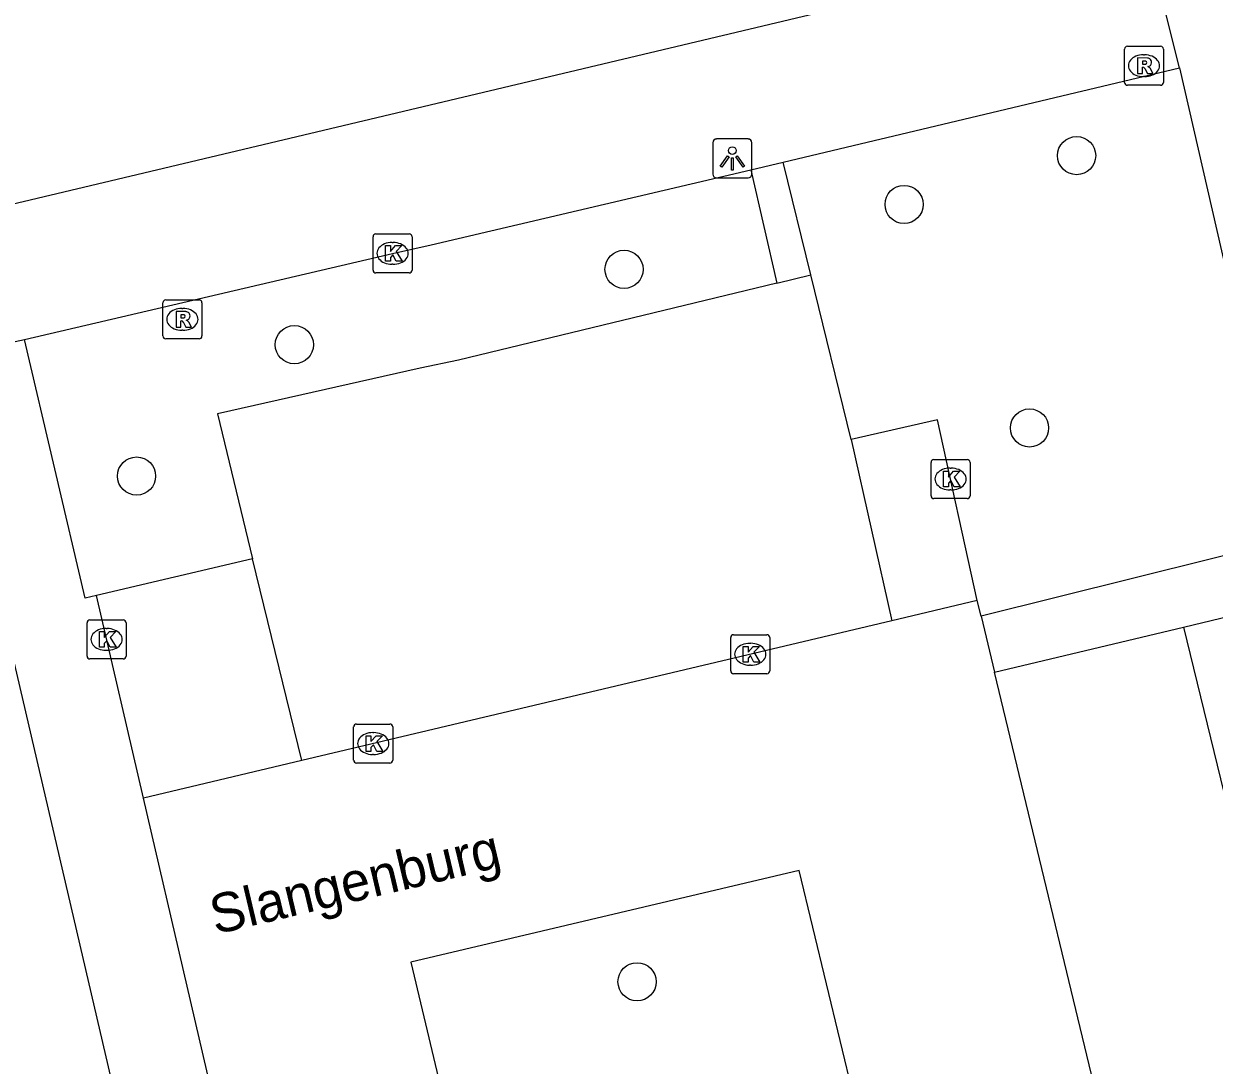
# Model space of a CAD drawing. Extents: x 158038 to 159242, y 380133 to 381214.
# Drawn here: x 158513.7 to 158544.2, y 380781.7 to 380808.39 of the extents above; entities that cross this region are included whole.
import ezdxf

# ---------------------------------------------------------------- set-up
doc = ezdxf.new("R2010")
doc.units = 0
for name, color, linetype in [('IMGEO_Boom', 7, 'Continuous'), ('IMGEO_Kolk', 7, 'Continuous'), ('IMGEO_Lichtpunt', 7, 'Continuous'), ('IMGEO_Openbare_ruimte_label', 7, 'Continuous'), ('IMGEO_Parkeervlak_open', 7, 'Continuous'), ('IMGEO_Rijbaan_lokaal_open', 7, 'Continuous'), ('IMGEO_Rioolput', 7, 'Continuous'), ('IMGEO_Voetpad_open', 7, 'Continuous')]:
    doc.layers.add(name, color=color, linetype=linetype)

msp = doc.modelspace()

# ---------------------------------------------------------------- linework, layer by layer
at = {"layer": 'IMGEO_Boom'}
for centre in [(158540.672, 380805.016), (158536.253, 380803.765), (158529.079, 380802.101), (158520.633, 380800.17), (158539.466, 380798.036), (158516.591, 380796.803), (158529.413, 380783.84)]:
    msp.add_circle(centre, 0.489, dxfattribs=at)
at = {"layer": 'IMGEO_Kolk'}
for p, q in [((158522.723, 380803.01), (158523.575, 380803.01)), ((158522.648, 380802.084), (158522.648, 380802.936)), ((158523.136, 380802.79), (158523.161, 380802.79)), ((158523.649, 380802.936), (158523.649, 380802.084)), ((158523.159, 380802.23), (158523.134, 380802.23)), ((158523.575, 380802.01), (158522.723, 380802.01)), ((158537.018, 380797.226), (158537.87, 380797.226)), ((158536.943, 380796.3), (158536.943, 380797.152)), ((158537.431, 380797.006), (158537.456, 380797.006)), ((158537.944, 380797.152), (158537.944, 380796.3)), ((158537.454, 380796.446), (158537.429, 380796.446)), ((158537.87, 380796.226), (158537.018, 380796.226)), ((158515.321, 380792.19), (158515.321, 380793.042)), ((158515.396, 380793.116), (158516.248, 380793.116)), ((158515.809, 380792.896), (158515.834, 380792.896)), ((158516.322, 380793.042), (158516.322, 380792.19)), ((158531.811, 380791.81), (158531.811, 380792.662)), ((158531.886, 380792.736), (158532.738, 380792.736)), ((158532.812, 380792.662), (158532.812, 380791.81)), ((158515.832, 380792.336), (158515.807, 380792.336)), ((158532.299, 380792.516), (158532.324, 380792.516)), ((158516.248, 380792.116), (158515.396, 380792.116)), ((158532.738, 380791.736), (158531.886, 380791.736)), ((158532.322, 380791.956), (158532.297, 380791.956)), ((158522.152, 380789.521), (158522.152, 380790.373)), ((158522.227, 380790.447), (158523.079, 380790.447)), ((158522.64, 380790.227), (158522.665, 380790.227)), ((158523.153, 380790.373), (158523.153, 380789.521)), ((158522.663, 380789.667), (158522.638, 380789.667)), ((158523.079, 380789.447), (158522.227, 380789.447))]:
    msp.add_line(p, q, dxfattribs=at)
for points in [[(158522.723, 380803.01), (158523.575, 380803.01)], [(158522.648, 380802.084), (158522.648, 380802.936)], [(158522.969, 380802.71), (158523.092, 380802.71), (158523.092, 380802.559), (158523.222, 380802.71), (158523.386, 380802.71), (158523.24, 380802.559), (158523.393, 380802.31), (158523.241, 380802.31), (158523.156, 380802.474), (158523.092, 380802.407), (158523.092, 380802.31), (158522.969, 380802.31), (158522.969, 380802.71)], [(158523.649, 380802.936), (158523.649, 380802.084)], [(158523.575, 380802.01), (158522.723, 380802.01)], [(158537.018, 380797.226), (158537.87, 380797.226)], [(158536.943, 380796.3), (158536.943, 380797.152)], [(158537.264, 380796.926), (158537.387, 380796.926), (158537.387, 380796.775), (158537.517, 380796.926), (158537.681, 380796.926), (158537.535, 380796.775), (158537.688, 380796.526), (158537.536, 380796.526), (158537.451, 380796.69), (158537.387, 380796.623), (158537.387, 380796.526), (158537.264, 380796.526), (158537.264, 380796.926)], [(158537.944, 380797.152), (158537.944, 380796.3)], [(158537.87, 380796.226), (158537.018, 380796.226)], [(158515.321, 380792.19), (158515.321, 380793.042)], [(158515.396, 380793.116), (158516.248, 380793.116)], [(158516.322, 380793.042), (158516.322, 380792.19)], [(158515.642, 380792.816), (158515.765, 380792.816), (158515.765, 380792.665), (158515.895, 380792.816), (158516.059, 380792.816), (158515.913, 380792.665), (158516.066, 380792.416), (158515.914, 380792.416), (158515.829, 380792.58), (158515.765, 380792.513), (158515.765, 380792.416), (158515.642, 380792.416), (158515.642, 380792.816)], [(158531.811, 380791.81), (158531.811, 380792.662)], [(158531.886, 380792.736), (158532.738, 380792.736)], [(158532.812, 380792.662), (158532.812, 380791.81)], [(158532.132, 380792.436), (158532.255, 380792.436), (158532.255, 380792.285), (158532.385, 380792.436), (158532.549, 380792.436), (158532.403, 380792.285), (158532.556, 380792.036), (158532.404, 380792.036), (158532.319, 380792.2), (158532.255, 380792.133), (158532.255, 380792.036), (158532.132, 380792.036), (158532.132, 380792.436)], [(158516.248, 380792.116), (158515.396, 380792.116)], [(158532.738, 380791.736), (158531.886, 380791.736)], [(158522.152, 380789.521), (158522.152, 380790.373)], [(158522.227, 380790.447), (158523.079, 380790.447)], [(158523.153, 380790.373), (158523.153, 380789.521)], [(158522.473, 380790.147), (158522.596, 380790.147), (158522.596, 380789.996), (158522.726, 380790.147), (158522.89, 380790.147), (158522.744, 380789.996), (158522.897, 380789.747), (158522.745, 380789.747), (158522.66, 380789.911), (158522.596, 380789.844), (158522.596, 380789.747), (158522.473, 380789.747), (158522.473, 380790.147)], [(158523.079, 380789.447), (158522.227, 380789.447)]]:
    msp.add_lwpolyline(points, dxfattribs=at)
for centre, start, end in [((158522.725, 380802.934), 91.552, 178.448), ((158522.725, 380802.934), 91.552, 178.448), ((158523.573, 380802.934), 1.552, 88.448), ((158523.573, 380802.934), 1.552, 88.448), ((158522.725, 380802.086), 181.552, 268.448), ((158522.725, 380802.086), 181.552, 268.448), ((158523.573, 380802.086), 271.552, 358.448), ((158523.573, 380802.086), 271.552, 358.448), ((158537.02, 380797.15), 91.552, 178.448), ((158537.02, 380797.15), 91.552, 178.448), ((158537.868, 380797.15), 1.552, 88.448), ((158537.868, 380797.15), 1.552, 88.448), ((158537.02, 380796.302), 181.552, 268.448), ((158537.02, 380796.302), 181.552, 268.448), ((158537.868, 380796.302), 271.552, 358.448), ((158537.868, 380796.302), 271.552, 358.448), ((158515.398, 380793.04), 91.552, 178.448), ((158515.398, 380793.04), 91.552, 178.448), ((158516.246, 380793.04), 1.552, 88.448), ((158516.246, 380793.04), 1.552, 88.448), ((158531.888, 380792.66), 91.552, 178.448), ((158531.888, 380792.66), 91.552, 178.448), ((158532.736, 380792.66), 1.552, 88.448), ((158532.736, 380792.66), 1.552, 88.448), ((158515.398, 380792.192), 181.552, 268.448), ((158515.398, 380792.192), 181.552, 268.448), ((158516.246, 380792.192), 271.552, 358.448), ((158516.246, 380792.192), 271.552, 358.448), ((158531.888, 380791.812), 181.552, 268.448), ((158531.888, 380791.812), 181.552, 268.448), ((158532.736, 380791.812), 271.552, 358.448), ((158532.736, 380791.812), 271.552, 358.448), ((158522.229, 380790.371), 91.552, 178.448), ((158522.229, 380790.371), 91.552, 178.448), ((158523.077, 380790.371), 1.552, 88.448), ((158523.077, 380790.371), 1.552, 88.448), ((158522.229, 380789.523), 181.552, 268.448), ((158522.229, 380789.523), 181.552, 268.448), ((158523.077, 380789.523), 271.552, 358.448), ((158523.077, 380789.523), 271.552, 358.448)]:
    msp.add_arc(centre, 0.0765, start, end, dxfattribs=at)
for centre, major_axis, ratio, start_param, end_param in [((158523.135, 380802.51), (-0.387, 0.002), 0.722429, 4.712389, 7.853982), ((158523.16, 380802.51), (-0.39, 0.002), 0.717154, 1.570796, 4.712389), ((158537.43, 380796.726), (-0.387, 0.002), 0.722429, 4.712389, 7.853982), ((158537.455, 380796.726), (-0.39, 0.002), 0.717154, 1.570796, 4.712389), ((158515.808, 380792.616), (-0.387, 0.002), 0.722429, 4.712389, 7.853982), ((158515.833, 380792.616), (-0.39, 0.002), 0.717154, 1.570796, 4.712389), ((158532.298, 380792.236), (-0.387, 0.002), 0.722429, 4.712389, 7.853982), ((158532.323, 380792.236), (-0.39, 0.002), 0.717154, 1.570796, 4.712389), ((158522.639, 380789.947), (-0.387, 0.002), 0.722429, 4.712389, 7.853982), ((158522.664, 380789.947), (-0.39, 0.002), 0.717154, 1.570796, 4.712389)]:
    msp.add_ellipse(centre, major_axis=major_axis, ratio=ratio, start_param=start_param, end_param=end_param, dxfattribs=at)
at = {"layer": 'IMGEO_Lichtpunt'}
for p, q in [((158532.257, 380805.442), (158531.449, 380805.442)), ((158532.257, 380805.442), (158531.449, 380805.442)), ((158531.355, 380805.347), (158531.355, 380804.54)), ((158531.355, 380805.347), (158531.355, 380804.54)), ((158532.351, 380804.54), (158532.351, 380805.347)), ((158532.351, 380804.54), (158532.351, 380805.347)), ((158531.449, 380804.446), (158532.257, 380804.446)), ((158531.449, 380804.446), (158532.257, 380804.446))]:
    msp.add_line(p, q, dxfattribs=at)
for points in [[(158531.729, 380805.011), (158531.768, 380804.983), (158531.58, 380804.721), (158531.542, 380804.748), (158531.729, 380805.011)], [(158531.831, 380804.963), (158531.878, 380804.963), (158531.878, 380804.641), (158531.831, 380804.641), (158531.831, 380804.963)], [(158531.941, 380804.983), (158531.979, 380805.01), (158532.166, 380804.748), (158532.127, 380804.72), (158531.941, 380804.983)]]:
    msp.add_lwpolyline(points, dxfattribs=at)
msp.add_circle((158531.854, 380805.145), 0.0994, dxfattribs=at)
for centre, start, end in [((158531.449, 380805.347), 90, 180), ((158531.449, 380805.347), 90, 180), ((158532.257, 380805.347), 0, 90), ((158532.257, 380805.347), 0, 90), ((158531.449, 380804.54), 180, 270), ((158531.449, 380804.54), 180, 270), ((158532.257, 380804.54), 270, 0), ((158532.257, 380804.54), 270, 360)]:
    msp.add_arc(centre, 0.0946, start, end, dxfattribs=at)
at = {"layer": 'IMGEO_Parkeervlak_open'}
for points in [[(158532.991, 380801.748), (158524.836, 380799.776), (158523.857, 380799.569), (158518.667, 380798.396), (158519.561, 380794.681)], [(158534.897, 380797.743), (158533.865, 380801.959)], [(158538.129, 380793.613), (158537.111, 380798.246), (158534.897, 380797.743)], [(158534.897, 380797.743), (158535.941, 380793.094)], [(158519.561, 380794.681), (158515.561, 380793.744)], [(158520.821, 380789.512), (158519.561, 380794.681)], [(158543.412, 380792.934), (158546.695, 380779.447), (158541.806, 380778.346)]]:
    msp.add_lwpolyline(points, dxfattribs=at)
at = {"layer": 'IMGEO_Rijbaan_lokaal_open'}
for points in [[(158538.129, 380793.613), (158535.941, 380793.094)], [(158538.226, 380793.212), (158538.129, 380793.613)], [(158538.226, 380793.212), (158538.573, 380791.773)], [(158535.941, 380793.094), (158520.821, 380789.512)], [(158541.806, 380778.346), (158538.573, 380791.773)], [(158520.821, 380789.512), (158516.767, 380788.551)], [(158525.882, 380749.276), (158525.714, 380750), (158516.767, 380788.551)], [(158533.569, 380786.69), (158523.615, 380784.341), (158529.274, 380760.557), (158530.311, 380756.201), (158540.327, 380758.659), (158537.07, 380772.17), (158533.569, 380786.69)]]:
    msp.add_lwpolyline(points, dxfattribs=at)
at = {"layer": 'IMGEO_Rioolput'}
for p, q in [((158541.898, 380806.894), (158541.898, 380807.746)), ((158541.973, 380807.82), (158542.825, 380807.82)), ((158542.386, 380807.6), (158542.411, 380807.6)), ((158542.899, 380807.746), (158542.899, 380806.894)), ((158542.409, 380807.04), (158542.384, 380807.04)), ((158542.825, 380806.82), (158541.973, 380806.82)), ((158517.264, 380800.393), (158517.264, 380801.245)), ((158517.339, 380801.319), (158518.191, 380801.319)), ((158518.265, 380801.245), (158518.265, 380800.393)), ((158517.752, 380801.099), (158517.777, 380801.099)), ((158517.775, 380800.539), (158517.75, 380800.539)), ((158518.191, 380800.319), (158517.339, 380800.319))]:
    msp.add_line(p, q, dxfattribs=at)
for points in [[(158541.898, 380806.894), (158541.898, 380807.746)], [(158541.973, 380807.82), (158542.825, 380807.82)], [(158542.899, 380807.746), (158542.899, 380806.894)], [(158542.487, 380807.518), (158542.235, 380807.52), (158542.235, 380807.12)], [(158542.235, 380807.12), (158542.359, 380807.12), (158542.359, 380807.282), (158542.37, 380807.282)], [(158542.413, 380807.439), (158542.359, 380807.439), (158542.359, 380807.358)], [(158542.359, 380807.358), (158542.411, 380807.358)], [(158542.417, 380807.253), (158542.488, 380807.12), (158542.628, 380807.12), (158542.563, 380807.246)], [(158542.825, 380806.82), (158541.973, 380806.82)], [(158517.264, 380800.393), (158517.264, 380801.245)], [(158517.339, 380801.319), (158518.191, 380801.319)], [(158518.265, 380801.245), (158518.265, 380800.393)], [(158517.853, 380801.017), (158517.601, 380801.019), (158517.601, 380800.619)], [(158517.779, 380800.938), (158517.725, 380800.938), (158517.725, 380800.857)], [(158517.725, 380800.857), (158517.777, 380800.857)], [(158517.601, 380800.619), (158517.725, 380800.619), (158517.725, 380800.781), (158517.736, 380800.781)], [(158517.783, 380800.752), (158517.854, 380800.619), (158517.994, 380800.619), (158517.929, 380800.745)], [(158518.191, 380800.319), (158517.339, 380800.319)]]:
    msp.add_lwpolyline(points, dxfattribs=at)
for centre, radius, start, end in [((158541.975, 380807.744), 0.0765, 91.552, 178.448), ((158541.975, 380807.744), 0.0765, 91.552, 178.448), ((158542.823, 380807.744), 0.0765, 1.552, 88.448), ((158542.823, 380807.744), 0.0765, 1.552, 88.448), ((158542.369, 380807.229), 0.0533, 26.0293, 88.6989), ((158542.395, 380807.547), 0.19, 274.7715, 282.9687), ((158542.419, 380807.343), 0.0964, 77.0061, 93.1865), ((158542.433, 380807.4), 0.0378, 276.6634, 79.6772), ((158542.486, 380807.408), 0.109, 350.3612, 89.416), ((158542.484, 380807.408), 0.112, 277.5842, 350.9817), ((158542.468, 380807.193), 0.108, 29.5134, 73.7905), ((158541.975, 380806.896), 0.0765, 181.552, 268.448), ((158541.975, 380806.896), 0.0765, 181.552, 268.448), ((158542.823, 380806.896), 0.0765, 271.552, 358.448), ((158542.823, 380806.896), 0.0765, 271.552, 358.448), ((158517.341, 380801.243), 0.0765, 91.552, 178.448), ((158517.341, 380801.243), 0.0765, 91.552, 178.448), ((158518.189, 380801.243), 0.0765, 1.552, 88.448), ((158518.189, 380801.243), 0.0765, 1.552, 88.448), ((158517.761, 380801.046), 0.19, 274.7715, 282.9687), ((158517.785, 380800.842), 0.0964, 77.0061, 93.1865), ((158517.799, 380800.899), 0.0378, 276.6634, 79.6772), ((158517.852, 380800.907), 0.109, 350.3612, 89.416), ((158517.85, 380800.907), 0.112, 277.5842, 350.9817), ((158517.735, 380800.728), 0.0533, 26.0293, 88.6989), ((158517.834, 380800.692), 0.108, 29.5134, 73.7905), ((158517.341, 380800.395), 0.0765, 181.552, 268.448), ((158517.341, 380800.395), 0.0765, 181.552, 268.448), ((158518.189, 380800.395), 0.0765, 271.552, 358.448), ((158518.189, 380800.395), 0.0765, 271.552, 358.448)]:
    msp.add_arc(centre, radius, start, end, dxfattribs=at)
for centre, major_axis, ratio, start_param, end_param in [((158542.385, 380807.32), (-0.387, 0.002), 0.722429, 4.712389, 7.853982), ((158542.41, 380807.32), (-0.39, 0.002), 0.717154, 1.570796, 4.712389), ((158517.751, 380800.819), (-0.387, 0.002), 0.722429, 4.712389, 7.853982), ((158517.776, 380800.819), (-0.39, 0.002), 0.717154, 1.570796, 4.712389)]:
    msp.add_ellipse(centre, major_axis=major_axis, ratio=ratio, start_param=start_param, end_param=end_param, dxfattribs=at)
at = {"layer": 'IMGEO_Voetpad_open'}
for points in [[(158543.309, 380807.269), (158542.451, 380810.679)], [(158506.764, 380802.198), (158510.799, 380803.157), (158537.922, 380809.603)], [(158533.158, 380804.845), (158543.309, 380807.269)], [(158543.309, 380807.269), (158546.085, 380795.171)], [(158532.331, 380804.649), (158533.158, 380804.845)], [(158533.865, 380801.959), (158533.158, 380804.845)], [(158513.72, 380800.306), (158523.146, 380802.508), (158524.138, 380802.728), (158532.331, 380804.649)], [(158532.331, 380804.649), (158532.991, 380801.748)], [(158532.991, 380801.748), (158533.865, 380801.959)], [(158511.631, 380799.863), (158513.72, 380800.306)], [(158515.561, 380793.744), (158515.274, 380793.677), (158513.72, 380800.306)], [(158522.019, 380748.055), (158522.172, 380748.116), (158522.319, 380748.19), (158522.458, 380748.277), (158522.589, 380748.376), (158522.711, 380748.487), (158522.823, 380748.607), (158522.923, 380748.738), (158523.011, 380748.877), (158523.087, 380749.023), (158523.149, 380749.175), (158523.197, 380749.332), (158523.231, 380749.493), (158523.251, 380749.657), (158523.255, 380749.821), (158523.246, 380749.985), (158523.244, 380750), (158511.631, 380799.863)], [(158546.085, 380795.171), (158538.226, 380793.212)], [(158516.767, 380788.551), (158515.561, 380793.744)], [(158543.412, 380792.934), (158546.49, 380793.669)], [(158538.573, 380791.773), (158543.412, 380792.934)]]:
    msp.add_lwpolyline(points, dxfattribs=at)

# ---------------------------------------------------------------- texts
at = {"layer": 'IMGEO_Openbare_ruimte_label'}
msp.add_text('Slangenburg', height=1, rotation=13.2996, dxfattribs=at).set_placement((158518.607, 380785.05))

doc.saveas('drawing.dxf')
